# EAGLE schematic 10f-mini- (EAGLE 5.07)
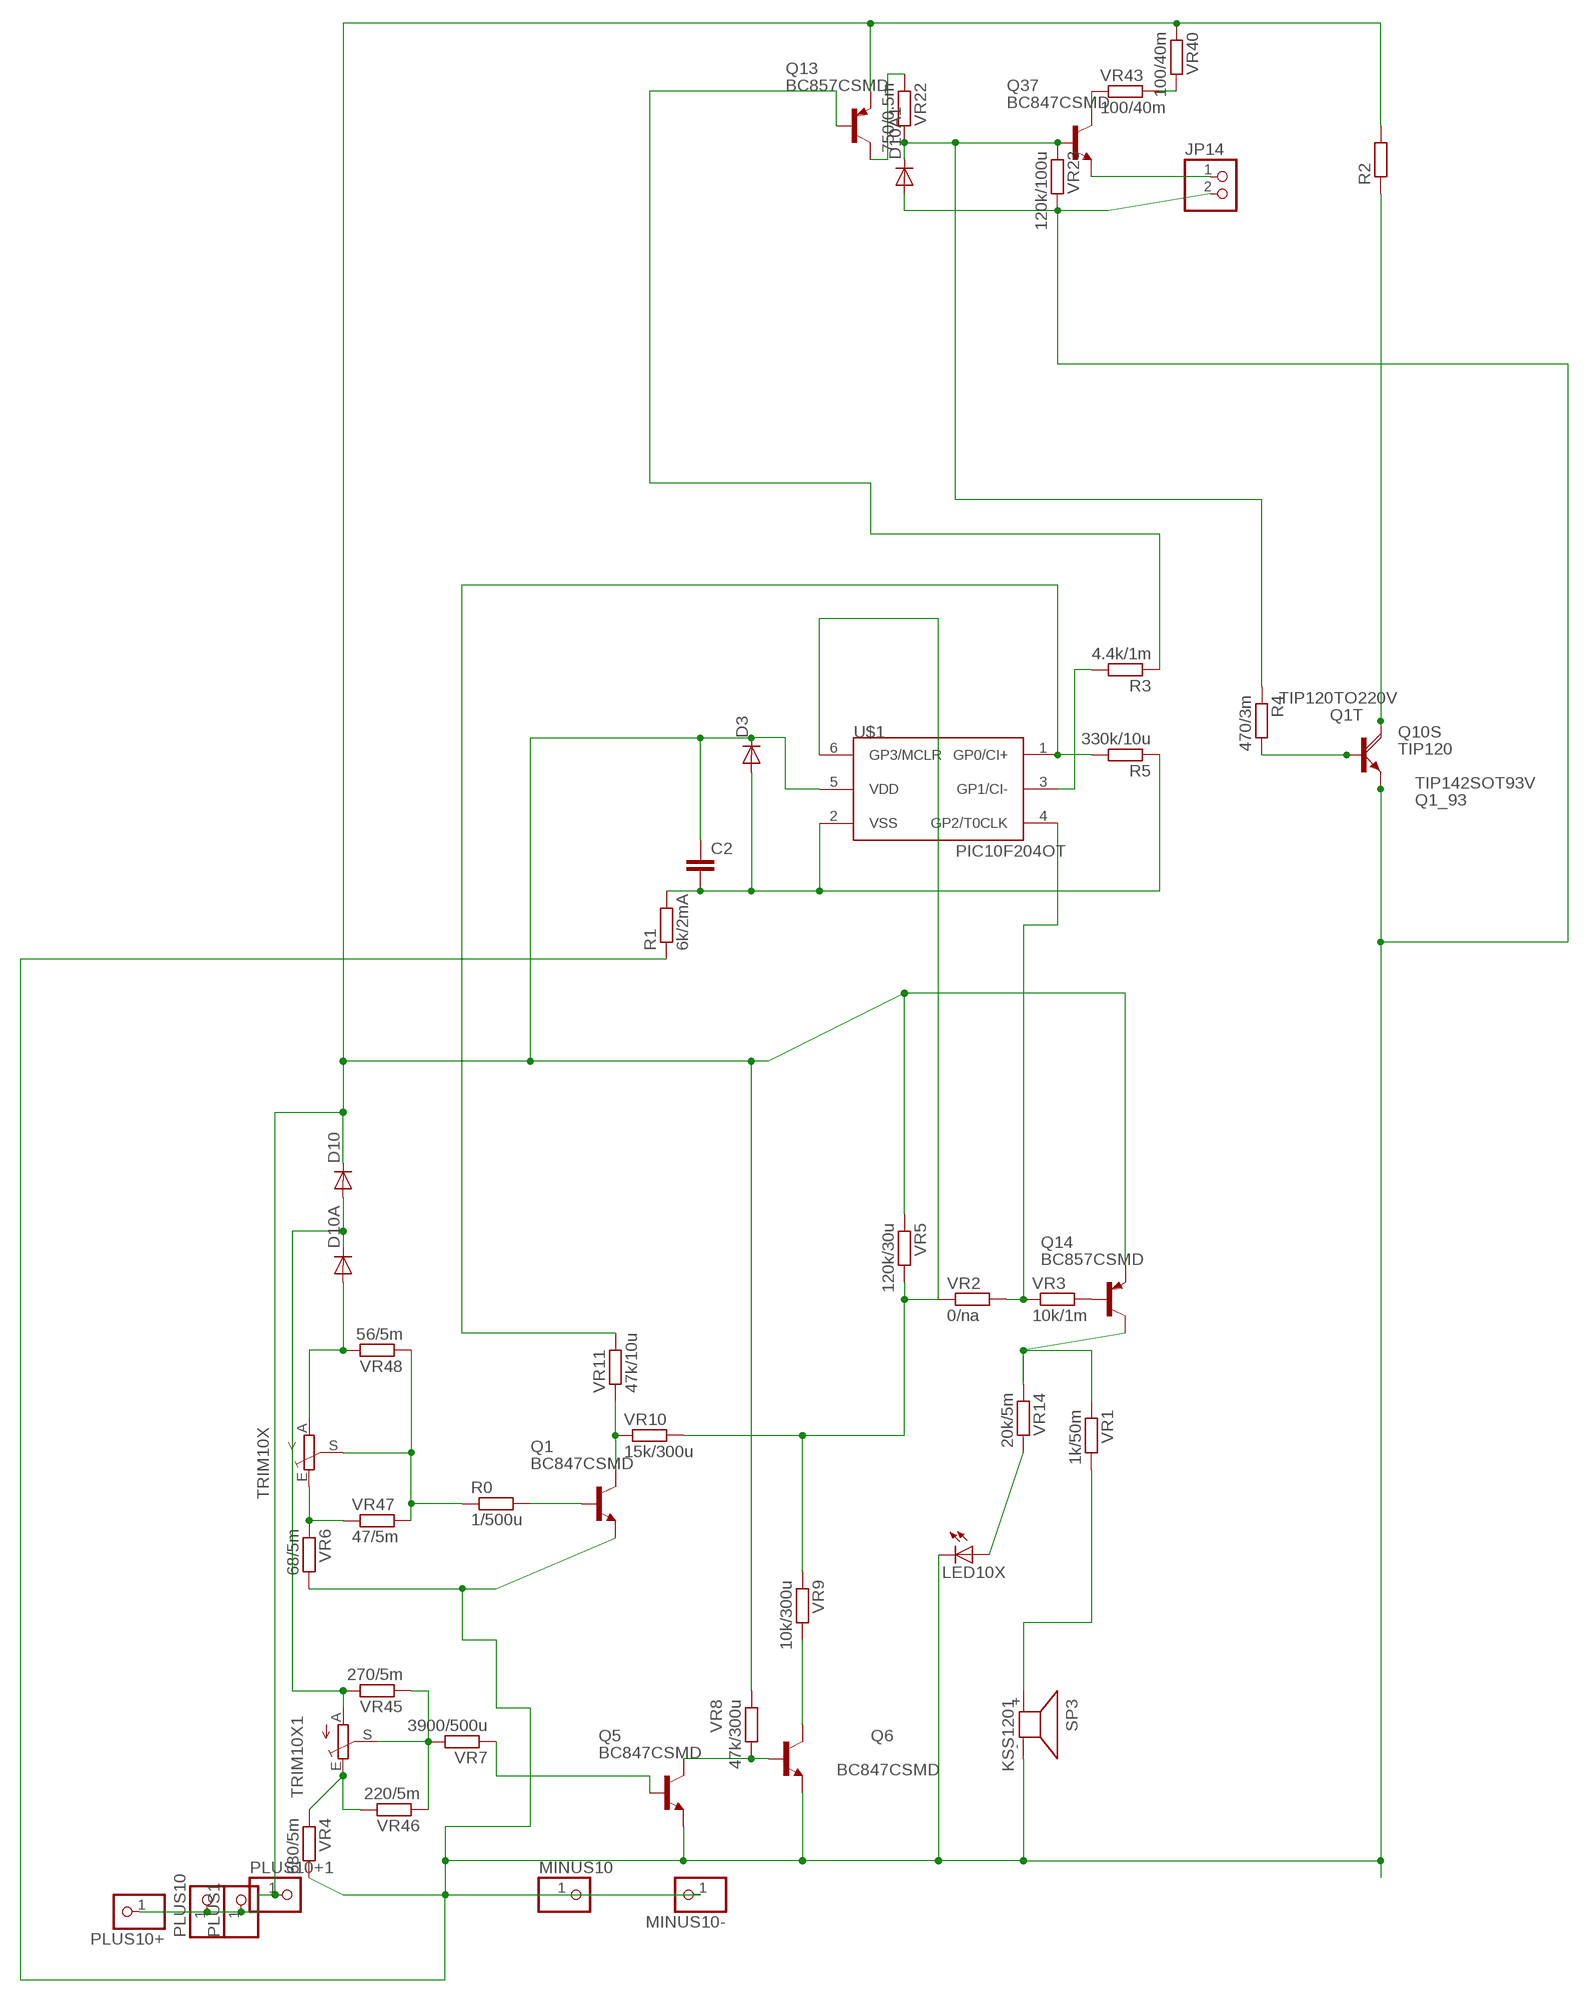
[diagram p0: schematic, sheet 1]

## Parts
C2  C-EUC0805  [C0805]
D3  DIODE-MINIMELF  [MINIMELF]
D10  DIODE-MINIMELF  [MINIMELF]
D10A  DIODE-MINIMELF  [MINIMELF]
D10A1  DIODE-MINIMELF  [MINIMELF]
JP14  PINHD-1X2STR  [1X02]
LED10X  LEDCHIPLED_1206  [CHIPLED_1206]
MINUS10  PINHD-1X14.5MM  [1X4MM5]
MINUS10-  PINHD-1X11X0.4  [1X01]
PLUS1  PINHD-1X14.5MM  [1X4MM5]
PLUS10  PINHD-1X14.5MM  [1X4MM5]
PLUS10+  PINHD-1X11X0.4  [1X01]
PLUS10+1  PINHD-1X11X0.4  [1X01]
Q1  BC847CSMD  [SOT23]
Q1_93  TIP142SOT93V  [SOT93V]
Q1T  TIP120TO220V  [TO220AV]
Q5  BC847CSMD  [SOT23]
Q6  BC847CSMD  [SOT23]
Q10S  TIP120  TIP120DPAK  [D-PAK_TO252AA]
Q13  BC857CSMD  [SOT23-BEC]
Q14  BC857CSMD  [SOT23-BEC]
Q37  BC847CSMD  [SOT23]
R0  1/500u  R-EU_R1206  [R1206]
R1  6k/2mA  R-EU_R0805  [R0805]
R2  R-EU_CERAM50  [CERAM50]
R3  4.4k/1m  R-EU_R0805  [R0805]
R4  470/3m  R-EU_R0805  [R0805]
R5  330k/10u  R-EU_R0805  [R0805]
SP3  KSS1201  KSS12017MM  [KSS1202]
TRIM10X  TRIM_EU-S64W  [S64W]
TRIM10X1  TRIM_EU-S64W  [S64W]
U$1  PIC10F204OT  [SOT23-6]
VR1  1k/50m  R-EU_R0805  [R0805]
VR2  0/na  R-EU_R0805  [R0805]
VR3  10k/1m  R-EU_R1206  [R1206]
VR4  680/5m  R-EU_R1206  [R1206]
VR5  120k/30u  R-EU_R0805  [R0805]
VR6  68/5m  R-EU_R1206  [R1206]
VR7  3900/500u  R-EU_M1206  [M1206]
VR8  47k/300u  R-EU_R1206  [R1206]
VR9  10k/300u  R-EU_R0805  [R0805]
VR10  15k/300u  R-EU_R1206  [R1206]
VR11  47k/10u  R-EU_R0805  [R0805]
VR14  20k/5m  R-EU_R0805  [R0805]
VR22  750/0.5m  R-EU_R0805  [R0805]
VR23  120k/100u  R-EU_R0805  [R0805]
VR40  100/40m  R-EU_R1206  [R1206]
VR43  100/40m  R-EU_R1206  [R1206]
VR45  270/5m  R-EU_R0805  [R0805]
VR46  220/5m  R-EU_R1206  [R1206]
VR47  47/5m  R-EU_R0805  [R0805]
VR48  56/5m  R-EU_R0805  [R0805]

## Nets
B: R0.1 TRIM10X.S VR47.2 VR48.1
BUZZ+: SP3.+ VR1.2
GP3: U$1.4(GP2/T0CLK) VR2.2 VR3.1
MIN-: C2.1 D3.C D10.C PLUS1.1 PLUS10+1.1 PLUS10+.1 PLUS10.1 Q13.E Q14.E R2.2 U$1.5(VDD) VR5.1 VR8.1 VR40.1
N$1: R3.2 U$1.3(GP1/CI-)
N$2: Q1.3(C) VR10.1 VR11.1
N$3: Q5.3(C) Q6.1(B) VR8.2
N$4: LED10X.A VR14.2
N$5: Q6.3(C) VR9.2
N$6: U$1.6(GP3/MCLR) VR2.1 VR5.2 VR9.1 VR10.2
N$7: Q1.1(B) R0.2
N$8: Q14.C VR1.1 VR14.1
N$10: Q14.B VR3.2
N$14: D10A.A TRIM10X.A VR48.2
N$17: D10.A D10A.C TRIM10X1.A VR45.2
N$22: TRIM10X1.S VR7.2 VR45.1 VR46.1
N$23: Q13.B R3.1
N$24: TRIM10X1.E VR4.1 VR46.2
N$25: Q1_93.B Q1T.B Q10S.1(B) R4.2
N$128: TRIM10X.E VR6.1 VR47.1
N$136: JP14.1 Q37.2(E)
N$138: R5.2 U$1.1(GP0/CI+) VR11.2
N$159: Q13.C VR22.1
N$163: VR40.2 VR43.2
N$164: Q37.3(C) VR43.1
N$168: Q5.1(B) VR7.1
N$179: D10A1.C Q37.1(B) R4.1 VR22.2 VR23.1
Q10C: Q1_93.C Q1T.C Q10S.4(C) R2.1
VSS: D10A1.A JP14.2 LED10X.C MINUS10-.1 MINUS10.1 Q1.2(E) Q1_93.E Q1T.E Q5.2(E) Q6.2(E) Q10S.3(E) R1.1 SP3.- VR4.2 VR6.2 VR23.2
VSS1: C2.2 D3.A R1.2 R5.1 U$1.2(VSS)

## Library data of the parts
C2 = rcl:C-EU: CAPACITOR, European symbol
D3 D10 D10A D10A1 = diode:DIODE-: DIODE
JP14 = pinhead:PINHD-1X2: PIN HEADER
LED10X = led:LED: LED
MINUS10 MINUS10- PLUS1 PLUS10 PLUS10+ PLUS10+1 = pinhead:PINHD-1X1: PIN HEADER
Q1 Q5 Q6 Q37 = transistor-npn:BC847*: NPN Transistor
Q1_93 = transistor-power:TIP142: NPN DARLINGTON TRANSISTOR
Q1T Q10S = transistor-power:TIP120: NPN DARLINGTON TRANSISTOR
Q13 Q14 = transistor-pnp:BC857*: PNP Transistror
R0 R1 R3-R5 VR1-VR11 VR14 VR22 VR23 VR40 VR43 VR45-VR48 = rcl-2:R-EU_: RESISTOR, European symbol
R2 = rcl:R-EU_: RESISTOR, European symbol
SP3 = buzzer:KSS1201: SPEAKER
TRIM10X TRIM10X1 = pot:TRIM_EU-: POTENTIOMETER
U$1 = microchip-3:PIC10F2*: uPC nW 0,25/0,5k Program Flash memory Comparator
